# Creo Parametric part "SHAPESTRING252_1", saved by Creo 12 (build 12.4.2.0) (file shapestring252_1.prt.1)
Units: Custom; MM, KILOGRAM, SECS

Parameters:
  PTC_WM_ITERATION = "0"
  PTC_WM_VERSION = "-.0"
  PTC_WM_LIFECYCLE_STATE = "In Work"
  PTC_WM_LIFECYCLE = "MO_CADDocument"
  PTC_WM_CREATED_BY = "Maximilian Roepper (Z0017RMS: MO)"
  PTC_WM_CREATED_ON = "18-Sep-26 11:36:42 AM"
  PTC_WM_MODIFIED_BY = "Maximilian Roepper (Z0017RMS: MO)"
  PTC_WM_MODIFIED_ON = "18-Sep-26 11:36:46 AM"
  PDMLINKNUMBER = "PDM000071454768"
  PTC_WM_NAME = "shapestring252_1.prt"
  PTC_WM_NUMBER = "PDM000071454768"

Other parameters: WEIGHT, WEIGHT_FACTOR, WEIGHT_ADD, _MASS_TEMP, _DIFF_TEMP, MC_ERRORS, SUPPLIER

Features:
  1. coordinate system
  2. datum plane "PRT_YZ"
  3. datum plane "PRT_XY"
  4. datum plane "PRT_XZ"
  5. coordinate system
  6. datum axis
  7. datum axis
  8. datum axis
  9. coordinate system
  10. imported feature
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
Other named items: PRT, SIEMENS_MO, DRW_VIEW_ORG, PRT_X, PRT_Y, PRT_Z, CS0, ROUGH_GROB

Layers: 00_STD_CSYS-KSYS, 01_STD_PLANES-EBENEN, 02_STD_AXES-ACHSEN, 03_STD_CSYS-KSYS, 24_IMPORT_FEAT-IMPORT_KE, INTFCLR

Surfaces: 1 plane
